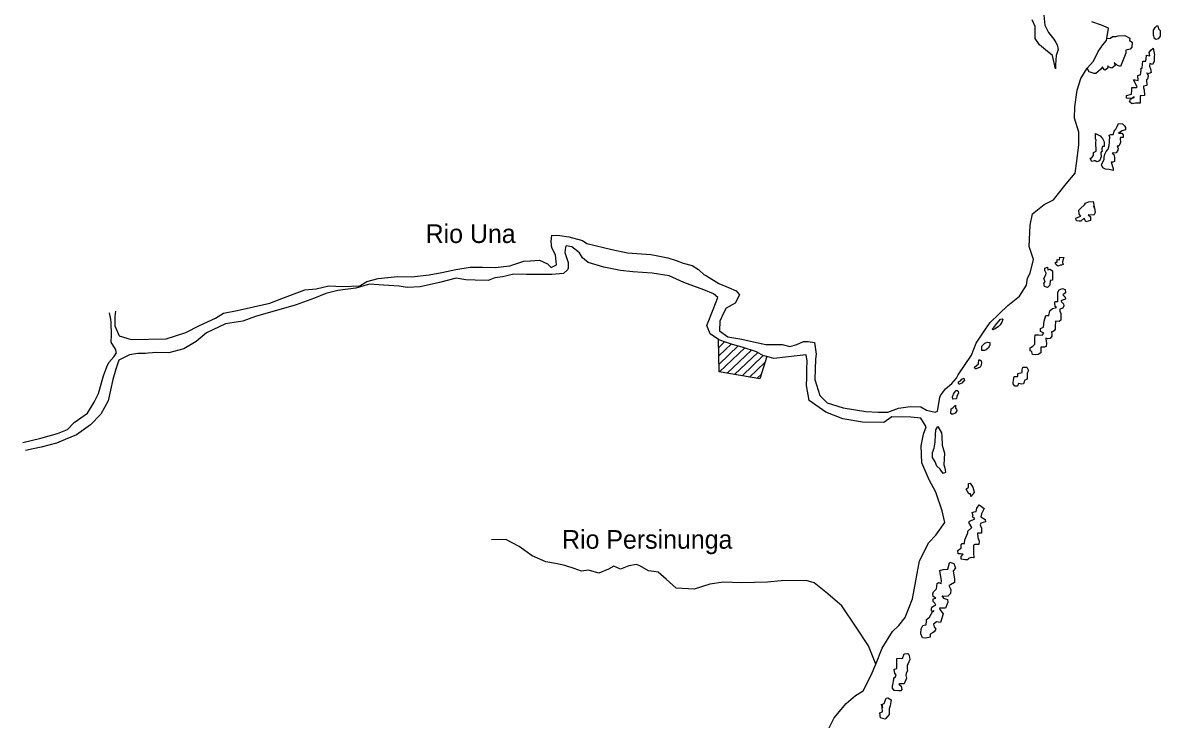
# Model space of a CAD drawing. Extents: x 662444 to 1640468, y 7452018 to 9606170.
# Drawn here: x 1556238 to 1598048, y 8997698 to 9023325 of the extents above; entities that cross this region are included whole.
import ezdxf

# ---------------------------------------------------------------- set-up
doc = ezdxf.new("R2010")
doc.units = 0
doc.layers.add('Level 1', color=7, linetype='Continuous')
doc.layers.add('Level 3', color=7, linetype='Continuous')

msp = doc.modelspace()

# ---------------------------------------------------------------- linework, layer by layer
at = {"layer": 'Level 1'}
for points in [[(1592448, 9012924), (1592877, 9013269), (1593130, 9013667), (1593169, 9013925), (1593271, 9014109), (1593389, 9014609), (1593232, 9015091), (1593269, 9015877), (1593352, 9016288), (1593781, 9016641), (1594125, 9016809), (1594585, 9017396), (1594920, 9017785), (1594987, 9018228), (1595051, 9018827), (1595056, 9019297), (1594900, 9019812), (1594911, 9020233), (1594992, 9020839), (1595132, 9021273), (1595361, 9021648), (1595593, 9021916), (1595764, 9022261), (1595941, 9022508), (1596074, 9022666), (1596142, 9023125), (1595886, 9023239), (1595534, 9023354)], [(1593763, 9023605), (1593809, 9023231), (1593939, 9022967), (1594135, 9022719), (1594205, 9022603), (1594259, 9022513), (1594294, 9022334), (1594225, 9022117), (1594199, 9021777), (1594195, 9021623), (1594088, 9022120), (1593834, 9022330), (1593612, 9022506), (1593456, 9022745), (1593445, 9023192), (1593337, 9023437)], [(1596087, 9022750), (1596222, 9022758), (1596296, 9022814), (1596417, 9022818), (1596507, 9022841), (1596742, 9022858), (1596925, 9022763), (1596914, 9022667), (1597010, 9022607), (1597005, 9022421), (1596938, 9022350), (1596784, 9022321), (1596781, 9022200), (1596591, 9021712), (1596478, 9021755), (1596360, 9021864), (1596390, 9021757), (1596265, 9021655), (1596137, 9021708), (1596122, 9021740), (1596112, 9021636), (1596005, 9021581), (1595943, 9021664), (1595919, 9021697), (1595852, 9021602), (1595686, 9021460), (1595621, 9021454), (1595430, 9021516), (1595361, 9021648)], [(1597801, 9022861), (1597804, 9022992), (1597798, 9023056), (1597865, 9023152), (1597923, 9023206), (1597955, 9023214), (1597984, 9023099), (1598016, 9023067), (1598048, 9023041), (1598042, 9022830), (1597967, 9022735), (1597886, 9022713), (1597838, 9022747), (1597808, 9022837), (1597801, 9022861)], [(1597668, 9022111), (1597639, 9022234), (1597698, 9022321), (1597788, 9022391), (1597838, 9022139), (1597829, 9022091), (1597824, 9021904), (1597764, 9021784), (1597668, 9021819), (1597650, 9021731), (1597695, 9021632), (1597708, 9021493), (1597577, 9021433), (1597554, 9021482), (1597600, 9021367), (1597580, 9021246), (1597547, 9021223), (1597558, 9021019), (1597428, 9020991), (1597426, 9020926), (1597457, 9020860), (1597468, 9020649), (1597346, 9020636), (1597314, 9020637), (1597306, 9020361), (1597137, 9020367), (1597016, 9020345), (1596920, 9020413), (1596955, 9020510), (1597086, 9020611), (1597053, 9020548), (1596899, 9020543), (1596802, 9020554), (1596805, 9020651), (1596993, 9020695), (1597004, 9020849), (1597007, 9020937), (1597177, 9020941), (1597201, 9020965), (1597063, 9021228), (1597127, 9021226), (1597232, 9021198), (1597229, 9021386), (1597294, 9021408), (1597326, 9021407), (1597347, 9021585), (1597332, 9021633), (1597381, 9021665), (1597413, 9021915), (1597517, 9021913), (1597535, 9022001), (1597539, 9022131), (1597668, 9022111)], [(1596518, 9019256), (1596631, 9019261), (1596686, 9019204), (1596683, 9019098), (1596586, 9019101), (1596577, 9019068), (1596590, 9018914), (1596530, 9018786), (1596465, 9018787), (1596495, 9018698), (1596493, 9018633), (1596426, 9018537), (1596280, 9018525), (1596336, 9018483), (1596366, 9018385), (1596370, 9018223), (1596304, 9018192), (1596239, 9018194), (1596323, 9017965), (1596321, 9017892), (1596167, 9017929), (1596030, 9017932), (1595934, 9017983), (1595889, 9018099), (1595924, 9018187), (1595983, 9018291), (1595985, 9018379), (1596012, 9018484), (1596055, 9018588), (1596130, 9018675), (1596174, 9018804), (1596177, 9018933), (1596187, 9018974), (1596199, 9019120), (1596176, 9019185), (1596234, 9019208), (1596314, 9019214), (1596358, 9019334), (1596417, 9019405), (1596459, 9019502), (1596512, 9019621), (1596657, 9019610), (1596735, 9019535), (1596773, 9019468), (1596771, 9019380), (1596650, 9019351), (1596518, 9019256)], [(1595681, 9018777), (1595675, 9018842), (1595684, 9018915), (1595687, 9019012), (1595671, 9019045), (1595665, 9019110), (1595669, 9019248), (1595844, 9019162), (1595931, 9019062), (1595992, 9018947), (1595988, 9018769), (1595923, 9018770), (1595896, 9018682), (1595918, 9018584), (1595886, 9018585), (1595860, 9018553), (1595880, 9018391), (1595812, 9018238), (1595715, 9018209), (1595659, 9018243), (1595626, 9018244), (1595528, 9018214), (1595467, 9018329), (1595533, 9018368), (1595591, 9018439), (1595594, 9018552), (1595692, 9018598), (1595696, 9018744), (1595681, 9018777)], [(1595396, 9016263), (1595483, 9016188), (1595488, 9016050), (1595309, 9015999), (1595255, 9016130), (1595132, 9016028), (1595067, 9016022), (1594970, 9016040), (1594941, 9016139), (1595095, 9016200), (1595128, 9016207), (1595065, 9016281), (1595061, 9016427), (1595112, 9016491), (1595261, 9016624), (1595302, 9016688), (1595416, 9016733), (1595579, 9016745), (1595623, 9016557), (1595598, 9016558), (1595637, 9016508), (1595650, 9016345), (1595606, 9016250), (1595396, 9016263)], [(1559649, 9012717), (1559627, 9012516), (1559622, 9012354), (1559627, 9012176), (1559779, 9011806), (1560219, 9011666), (1561512, 9011695), (1562228, 9011927), (1562735, 9012181), (1563323, 9012457), (1563619, 9012635), (1564114, 9012742), (1565316, 9013002), (1565765, 9013184), (1566612, 9013502), (1567017, 9013539), (1567488, 9013640), (1568005, 9013626), (1568626, 9013641), (1568889, 9013805), (1569304, 9013915), (1570009, 9013993), (1570525, 9013979), (1571181, 9014050), (1571636, 9014135), (1572156, 9014251), (1572683, 9014334), (1573143, 9014330), (1573603, 9014316), (1574146, 9014383), (1574659, 9014547), (1574894, 9014565), (1575234, 9014588), (1575521, 9014451), (1575663, 9014325), (1575852, 9014418), (1575820, 9014783), (1575690, 9015038), (1575663, 9015273), (1575686, 9015508), (1575984, 9015491), (1576314, 9015450), (1576812, 9015307), (1576971, 9015205), (1577893, 9014978), (1578464, 9014857), (1579318, 9014801), (1579576, 9014745), (1579953, 9014670), (1580250, 9014581), (1580507, 9014485), (1580843, 9014394), (1581082, 9014242), (1581271, 9014067), (1581375, 9014007), (1581819, 9013728), (1582179, 9013588), (1582466, 9013466), (1582584, 9013310), (1582423, 9013006), (1582094, 9012821), (1581993, 9012637), (1581864, 9012341), (1581847, 9011985), (1582156, 9011766), (1582663, 9011678), (1582992, 9011604), (1583554, 9011484), (1584152, 9011492), (1584433, 9011419), (1584693, 9011485), (1584931, 9011600), (1584987, 9011599), (1585108, 9011596), (1585334, 9011565), (1585395, 9011126), (1585382, 9010948), (1585355, 9010202), (1585533, 9009606), (1585800, 9009340), (1586393, 9009152), (1587230, 9009024), (1587682, 9009003), (1588037, 9009002), (1588428, 9009145), (1588851, 9009206), (1589246, 9009195), (1589461, 9009076), (1589774, 9008995), (1589864, 9009033), (1589950, 9009540), (1589968, 9009605), (1590152, 9009859), (1590384, 9010056), (1590559, 9010245), (1590619, 9010365), (1591106, 9011089), (1591287, 9011530), (1591624, 9012055), (1591792, 9012302), (1592448, 9012924)], [(1588203, 9000932), (1588435, 9001144), (1588669, 9001438), (1588946, 9002135), (1589069, 9002788), (1589193, 9003522), (1589542, 9004202), (1589800, 9004470), (1590127, 9004932), (1590034, 9005372), (1589802, 9006059), (1589554, 9006503), (1589289, 9007136), (1589264, 9007760), (1589341, 9008187), (1589445, 9008460), (1589244, 9008782), (1588880, 9008809), (1588187, 9008827), (1587890, 9008616), (1587099, 9008631), (1586383, 9008747), (1585751, 9008992), (1585148, 9009430), (1585049, 9009976), (1585057, 9010259), (1585058, 9010576), (1585066, 9010875), (1585039, 9011103), (1584699, 9011071), (1583839, 9010966), (1583583, 9011046), (1583470, 9011073), (1583207, 9011218), (1582687, 9011386), (1582326, 9011485), (1581989, 9011592), (1581806, 9011670), (1581505, 9011881), (1581383, 9012183), (1581616, 9012769), (1581790, 9013218), (1581624, 9013352), (1581272, 9013499), (1580536, 9013771), (1579993, 9014013), (1579374, 9014111), (1578664, 9014162), (1578205, 9014207), (1577594, 9014337), (1577025, 9014507), (1576812, 9014674), (1576703, 9014856), (1576426, 9015083), (1576217, 9015121), (1576184, 9015064), (1576162, 9014871), (1576282, 9014503), (1576284, 9014300), (1576259, 9014237), (1576109, 9014103), (1575689, 9014066), (1575099, 9014057), (1574751, 9014067), (1574284, 9014071), (1573877, 9013977), (1573594, 9013936), (1573348, 9013845), (1572864, 9013859), (1572525, 9013868), (1572163, 9013927), (1571562, 9013764), (1570847, 9013613), (1570370, 9013587), (1570072, 9013627), (1569492, 9013667), (1568984, 9013705), (1568479, 9013556), (1567823, 9013477), (1567384, 9013359), (1566960, 9013192), (1566283, 9012952), (1565909, 9012833), (1565177, 9012633), (1564795, 9012514), (1564330, 9012340), (1563689, 9012244), (1562994, 9011915), (1562615, 9011600), (1562164, 9011330), (1561603, 9011183), (1561167, 9011194), (1560844, 9011171), (1560747, 9011157), (1560473, 9011156), (1560165, 9011108), (1559764, 9010916), (1559658, 9010579), (1559552, 9010201), (1559378, 9009420), (1559107, 9008925)], [(1594350, 9014607), (1594352, 9014672), (1594361, 9014704), (1594498, 9014683), (1594472, 9014595), (1594452, 9014498), (1594475, 9014433), (1594417, 9014402), (1594385, 9014402), (1594296, 9014373), (1594225, 9014416), (1594194, 9014481), (1594195, 9014513), (1594260, 9014520), (1594261, 9014609), (1594350, 9014607)], [(1594007, 9013838), (1593995, 9013675), (1593903, 9013589), (1593792, 9013625), (1593763, 9013756), (1593819, 9013786), (1593789, 9013852), (1593767, 9013917), (1593843, 9014045), (1593853, 9014109), (1593806, 9014208), (1593801, 9014298), (1593899, 9014327), (1593921, 9014238), (1593986, 9014259), (1594089, 9014201), (1594092, 9013997), (1594090, 9013932), (1594088, 9013851), (1594007, 9013838)], [(1593770, 9011899), (1593642, 9011968), (1593645, 9012081), (1593751, 9012119), (1593782, 9012344), (1593843, 9012554), (1593957, 9012559), (1593985, 9012727), (1594085, 9012814), (1594240, 9012843), (1594184, 9012885), (1594179, 9013014), (1594181, 9013071), (1594278, 9013069), (1594284, 9013320), (1594286, 9013416), (1594338, 9013496), (1594452, 9013542), (1594548, 9013515), (1594569, 9013384), (1594470, 9013314), (1594509, 9013280), (1594548, 9013223), (1594563, 9013150), (1594416, 9013105), (1594407, 9013073), (1594493, 9012981), (1594507, 9012915), (1594465, 9012820), (1594359, 9012782), (1594357, 9012717), (1594395, 9012628), (1594397, 9012376), (1594331, 9012338), (1594202, 9012341), (1594189, 9012155), (1594186, 9012050), (1594152, 9011985), (1594086, 9011955), (1594054, 9011956), (1594059, 9011859), (1594066, 9011794), (1593999, 9011706), (1593910, 9011700), (1593846, 9011719), (1593845, 9011686), (1593865, 9011540), (1593854, 9011418), (1593821, 9011395), (1593789, 9011388), (1593659, 9011391), (1593662, 9011180), (1593564, 9011118), (1593474, 9011105), (1593353, 9011116), (1593332, 9011214), (1593300, 9011239), (1593268, 9011248), (1593271, 9011369), (1593370, 9011424), (1593436, 9011495), (1593440, 9011657), (1593442, 9011722), (1593445, 9011843), (1593574, 9011839), (1593704, 9011836), (1593770, 9011899)], [(1556238, 9007877), (1556905, 9008046), (1557515, 9008215), (1557881, 9008359), (1558130, 9008612), (1558623, 9008963), (1558868, 9009370), (1559021, 9009689), (1559208, 9010340), (1559330, 9010669), (1559407, 9010829), (1559581, 9011027), (1559690, 9011177), (1559645, 9011316), (1559489, 9011572), (1559496, 9011838), (1559493, 9012293), (1559479, 9012414), (1559428, 9012651)], [(1592162, 9012210), (1592087, 9012132), (1591955, 9012046), (1591890, 9012023), (1591875, 9012056), (1591934, 9012112), (1592043, 9012263), (1592133, 9012358), (1592175, 9012421), (1592240, 9012436), (1592256, 9012403), (1592229, 9012306), (1592162, 9012210)], [(1583583, 9011046), (1583335, 9010225), (1581839, 9010477), (1581806, 9011670)], [(1581815, 9011369), (1582049, 9011591)], [(1591719, 9011348), (1591653, 9011292), (1591587, 9011271), (1591490, 9011265), (1591492, 9011329), (1591494, 9011427), (1591602, 9011537), (1591635, 9011544), (1591700, 9011567), (1591782, 9011565), (1591787, 9011467), (1591719, 9011348)], [(1581823, 9011068), (1582291, 9011513)], [(1581831, 9010766), (1582533, 9011435)], [(1581851, 9010476), (1582776, 9011358)], [(1582126, 9010429), (1583018, 9011280)], [(1582402, 9010382), (1583252, 9011194)], [(1582677, 9010336), (1583458, 9011080)], [(1582953, 9010289), (1583517, 9010828)], [(1591372, 9010781), (1591385, 9010927), (1591417, 9010926), (1591464, 9010884), (1591478, 9010819), (1591460, 9010723), (1591426, 9010651), (1591279, 9010590), (1591247, 9010591), (1591224, 9010656), (1591372, 9010781)], [(1583228, 9010243), (1583386, 9010393)], [(1592840, 9010052), (1592797, 9009948), (1592709, 9009959), (1592637, 9010042), (1592638, 9010074), (1592658, 9010170), (1592677, 9010308), (1592806, 9010304), (1592815, 9010329), (1592817, 9010425), (1592972, 9010461), (1592975, 9010559), (1593001, 9010656), (1593139, 9010652), (1593209, 9010528), (1593157, 9010433), (1593156, 9010400), (1593152, 9010230), (1593135, 9010198), (1593070, 9010175), (1593053, 9010144), (1593026, 9010039), (1592961, 9010033), (1592840, 9010052)], [(1590797, 9010109), (1590781, 9010077), (1590675, 9010031), (1590642, 9010032), (1590634, 9010065), (1590635, 9010113), (1590701, 9010152), (1590752, 9010208), (1590834, 9010254), (1590855, 9010155), (1590797, 9010109)], [(1590565, 9009580), (1590555, 9009483), (1590425, 9009479), (1590411, 9009560), (1590446, 9009657), (1590480, 9009720), (1590547, 9009800), (1590579, 9009798), (1590626, 9009765), (1590633, 9009700), (1590565, 9009580)], [(1590576, 9009045), (1590509, 9008957), (1590395, 9008912), (1590346, 9008946), (1590367, 9009116), (1590425, 9009162), (1590524, 9009257), (1590521, 9009127), (1590553, 9009119), (1590576, 9009045)], [(1559107, 9008925), (1558734, 9008531), (1558215, 9008164), (1557799, 9007989), (1557474, 9007852), (1556921, 9007713), (1556621, 9007649), (1556345, 9007591)], [(1590122, 9007485), (1590101, 9007283), (1590095, 9007056), (1590117, 9006990), (1590138, 9006876), (1590152, 9006779), (1590070, 9006741), (1589953, 9006898), (1589835, 9007014), (1589774, 9007170), (1589681, 9007327), (1589671, 9007514), (1589739, 9007674), (1589777, 9007891), (1589793, 9008159), (1589798, 9008345), (1589874, 9008465), (1590013, 9008234), (1590017, 9008112), (1590033, 9007787), (1590122, 9007485)], [(1590920, 9006166), (1590994, 9006237), (1590998, 9006374), (1591063, 9006389), (1591156, 9006233), (1591192, 9006102), (1591206, 9006036), (1591082, 9005894), (1591077, 9005991), (1591012, 9005993), (1590920, 9006166)], [(1591153, 9005133), (1591167, 9005170), (1591131, 9005301), (1591212, 9005331), (1591285, 9005345), (1591305, 9005466), (1591388, 9005586), (1591476, 9005526), (1591571, 9005458), (1591477, 9005259), (1591458, 9005146), (1591617, 9005052), (1591623, 9004963), (1591452, 9004911), (1591433, 9004846), (1591479, 9004724), (1591482, 9004545), (1591329, 9004549), (1591341, 9004387), (1591386, 9004248), (1591383, 9004127), (1591229, 9004131), (1591188, 9004099), (1591183, 9003905), (1591189, 9003840), (1591191, 9003637), (1591095, 9003649), (1591005, 9003611), (1590971, 9003562), (1590882, 9003565), (1590730, 9003585), (1590732, 9003683), (1590800, 9003778), (1590710, 9003780), (1590622, 9003782), (1590609, 9003905), (1590667, 9003960), (1590733, 9003991), (1590736, 9004112), (1590769, 9004168), (1590858, 9004166), (1590862, 9004304), (1590904, 9004391), (1590974, 9004560), (1590975, 9004616), (1591124, 9004758), (1591008, 9004939), (1591050, 9004986), (1591229, 9005071), (1591213, 9005115), (1591153, 9005133)], [(1587598, 8999725), (1587325, 9000406), (1586874, 9001083), (1586346, 9001867), (1585754, 9002370), (1585327, 9002715), (1585030, 9002803), (1584117, 9002796), (1583614, 9002738), (1582661, 9002723), (1581991, 9002742), (1581497, 9002667), (1580918, 9002488), (1580258, 9002522), (1579886, 9002849), (1579594, 9003108), (1579434, 9003137), (1579240, 9003159), (1578922, 9003346), (1578795, 9003398), (1578510, 9003341), (1578208, 9003220), (1577961, 9003332), (1577772, 9003216), (1577413, 9003072), (1577028, 9003179), (1576776, 9003146), (1576512, 9003250), (1576160, 9003357), (1575815, 9003424), (1575469, 9003490), (1574966, 9003714), (1574483, 9004051), (1573989, 9004308), (1573472, 9004298)], [(1589995, 9002689), (1590005, 9002795), (1589951, 9003170), (1590065, 9003207), (1590243, 9003226), (1590306, 9003451), (1590315, 9003483), (1590459, 9003431), (1590519, 9003259), (1590436, 9003163), (1590483, 9002847), (1590480, 9002734), (1590341, 9002648), (1590276, 9002617), (1590345, 9002478), (1590333, 9002323), (1590241, 9002229), (1590047, 9002218), (1590015, 9002243), (1590077, 9002153), (1590230, 9002099), (1590235, 9002011), (1590149, 9001786), (1589938, 9001792), (1589945, 9001735), (1590071, 9001577), (1589965, 9001256), (1589828, 9001284), (1589712, 9001199), (1589734, 9001101), (1589805, 9001018), (1589737, 9000914), (1589672, 9000875), (1589590, 9000828), (1589587, 9000748), (1589587, 9000715), (1589433, 9000688), (1589311, 9000691), (1589251, 9000839), (1589256, 9001025), (1589324, 9001144), (1589414, 9001174), (1589446, 9001173), (1589457, 9001302), (1589459, 9001375), (1589566, 9001454), (1589693, 9001677), (1589726, 9001700), (1589684, 9001653), (1589637, 9001687), (1589640, 9001784), (1589674, 9001839), (1589731, 9001878), (1589796, 9001901), (1589765, 9001967), (1589702, 9002033), (1589705, 9002130), (1589803, 9002160), (1589707, 9002220), (1589694, 9002317), (1589712, 9002389), (1589828, 9002500), (1589850, 9002694), (1589899, 9002733), (1589995, 9002689)], [(1585778, 8997183), (1586058, 8997750), (1586509, 8998281), (1586848, 8998571), (1587128, 8998750), (1587425, 8999317), (1587598, 8999725), (1587832, 9000319), (1588203, 9000932)], [(1588442, 8998996), (1588521, 8998913), (1588551, 8998799), (1588517, 8998743), (1588428, 8998745), (1588266, 8998751), (1588212, 8998841), (1588206, 8998939), (1588216, 8998971), (1588261, 8999156), (1588255, 8999220), (1588312, 8999260), (1588346, 8999315), (1588291, 8999398), (1588262, 8999512), (1588263, 8999544), (1588360, 8999566), (1588361, 8999874), (1588363, 8999939), (1588508, 8999951), (1588572, 8999933), (1588634, 9000102), (1588755, 9000115), (1588787, 9000114), (1588818, 9000048), (1588838, 8999894), (1588786, 8999749), (1588743, 8999693), (1588748, 8999556), (1588762, 8999483), (1588704, 8999394), (1588693, 8999306), (1588722, 8999208), (1588636, 8998999), (1588459, 8999004), (1588442, 8998996)], [(1587837, 8998122), (1587841, 8998259), (1587906, 8998275), (1587968, 8998475), (1588033, 8998481), (1588161, 8998412), (1588122, 8998187), (1588087, 8998082), (1588081, 8997871), (1587940, 8997706), (1587763, 8997751), (1587744, 8997938), (1587833, 8997976), (1587822, 8998147), (1587808, 8998260), (1587837, 8998122)]]:
    msp.add_lwpolyline(points, dxfattribs=at)

# ---------------------------------------------------------------- texts
at = {"layer": 'Level 3'}
for s, height, p in [('Rio Una', 684.7, (1571047, 9015221)), ('Rio Persinunga', 684.66, (1576062, 9003973))]:
    msp.add_text(s, height=height, dxfattribs=at).set_placement(p)

doc.saveas('drawing.dxf')
